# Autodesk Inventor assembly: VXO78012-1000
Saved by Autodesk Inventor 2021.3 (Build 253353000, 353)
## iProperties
Created: 2022-06
Part Number: VXO78012-1000
Document SubType Name: Assembly
Designer: Administrator
Title: VXO78012-1000
Author: Administrator
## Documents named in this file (2)
- c:\worker\convert-fusion-r03\tmp\job-1\203\output\files\98ba3c1f-9f0e-47fe-8659-38db50984f0d\VXO78012-1000.iam
- c:\worker\convert-fusion-r03\tmp\job-1\203\output\files\98ba3c1f-9f0e-47fe-8659-38db50984f0d\COMPOUND (1).ipt
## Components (1 placed, 1 different names)
1. COMPOUND (1):1
